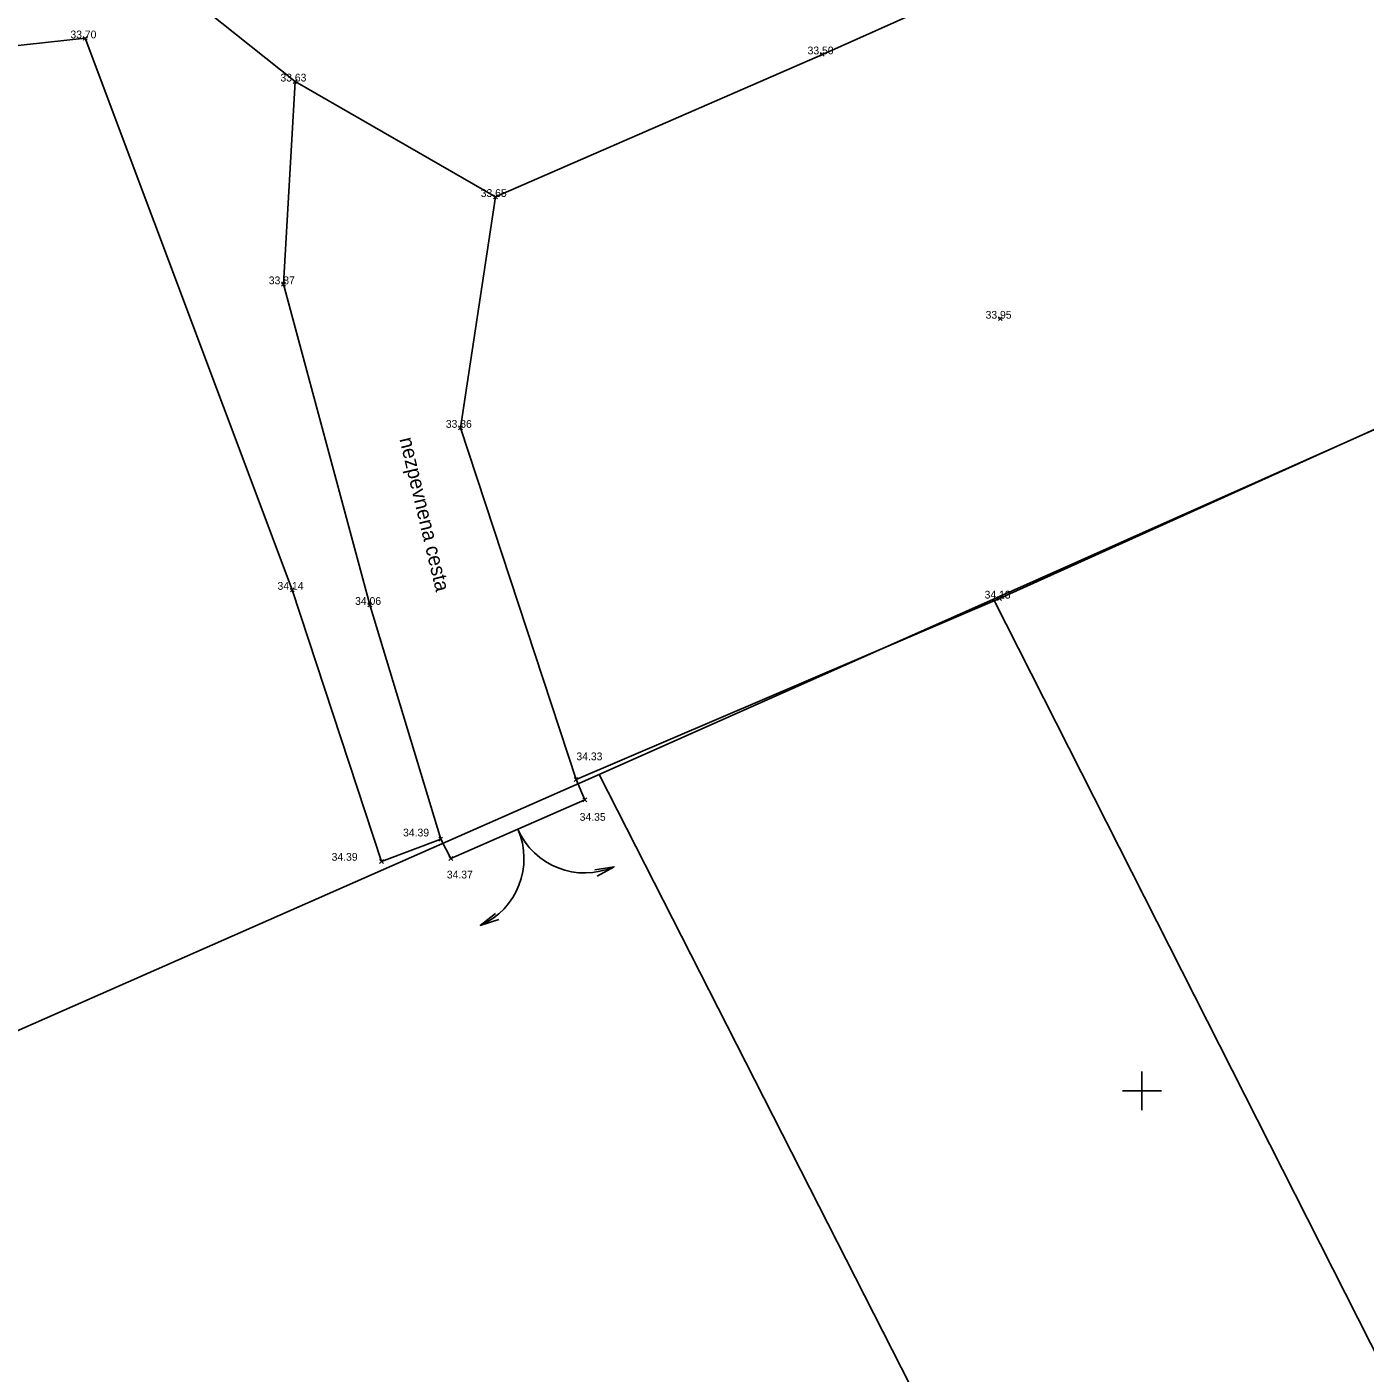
# Model space of a CAD drawing. Extents: x -772865 to -772533, y -1034366 to -1034132.
# Drawn here: x -772747.99 to -772720.4, y -1034305.82 to -1034278.06 of the extents above; entities that cross this region are included whole.
import ezdxf

# ---------------------------------------------------------------- set-up
doc = ezdxf.new("R2010")
doc.units = 0
for name, color, linetype in [('body', 7, 'Continuous'), ('KM_hranice', 7, 'Continuous'), ('mistni_popis', 7, 'Continuous'), ('oddeleni_ploch', 7, 'Continuous'), ('oploceni', 7, 'Continuous'), ('souradnicova_sit', 7, 'Continuous'), ('stromy_kere', 7, 'Continuous'), ('vyskove_koty', 7, 'Continuous')]:
    doc.layers.add(name, color=color, linetype=linetype)

msp = doc.modelspace()

# ---------------------------------------------------------------- linework, layer by layer
at = {"layer": 'body'}
for p, q in [((-772746.75, -1034278.34), (-772746.83, -1034278.26)), ((-772746.83, -1034278.34), (-772746.75, -1034278.26)), ((-772731.55, -1034278.67), (-772731.63, -1034278.59)), ((-772731.63, -1034278.67), (-772731.55, -1034278.59)), ((-772742.42, -1034279.23), (-772742.5, -1034279.15)), ((-772742.5, -1034279.23), (-772742.42, -1034279.15)), ((-772738.29, -1034281.61), (-772738.37, -1034281.53)), ((-772738.37, -1034281.61), (-772738.29, -1034281.53)), ((-772742.66, -1034283.41), (-772742.74, -1034283.33)), ((-772742.74, -1034283.41), (-772742.66, -1034283.33)), ((-772727.88, -1034284.12), (-772727.96, -1034284.04)), ((-772727.96, -1034284.12), (-772727.88, -1034284.04)), ((-772739.01, -1034286.37), (-772739.09, -1034286.29)), ((-772739.09, -1034286.37), (-772739.01, -1034286.29)), ((-772742.48, -1034289.71), (-772742.56, -1034289.63)), ((-772742.56, -1034289.71), (-772742.48, -1034289.63)), ((-772727.9, -1034289.89), (-772727.98, -1034289.81)), ((-772727.98, -1034289.89), (-772727.9, -1034289.81)), ((-772740.88, -1034290.02), (-772740.96, -1034289.94)), ((-772740.96, -1034290.02), (-772740.88, -1034289.94)), ((-772736.63, -1034293.62), (-772736.71, -1034293.54)), ((-772736.71, -1034293.62), (-772736.63, -1034293.54)), ((-772736.45, -1034294.04), (-772736.53, -1034293.96)), ((-772736.53, -1034294.04), (-772736.45, -1034293.96)), ((-772739.42, -1034294.85), (-772739.5, -1034294.77)), ((-772739.5, -1034294.85), (-772739.42, -1034294.77)), ((-772739.21, -1034295.25), (-772739.29, -1034295.17)), ((-772739.29, -1034295.25), (-772739.21, -1034295.17)), ((-772740.64, -1034295.31), (-772740.72, -1034295.23)), ((-772740.72, -1034295.31), (-772740.64, -1034295.23))]:
    msp.add_line(p, q, dxfattribs=at)
at = {"layer": 'KM_hranice'}
for p, q in [((-772728.06, -1034289.86), (-772677.97, -1034267.58)), ((-772728.06, -1034289.86), (-772736.19, -1034293.48)), ((-772709.03, -1034327.44), (-772728.06, -1034289.86)), ((-772736.19, -1034293.48), (-772790.73, -1034317.48)), ((-772720.86, -1034323.59), (-772736.19, -1034293.48))]:
    msp.add_line(p, q, dxfattribs=at)
at = {"layer": 'oddeleni_ploch'}
for p, q in [((-772738.33, -1034281.57), (-772739.05, -1034286.33)), ((-772739.05, -1034286.33), (-772736.67, -1034293.58)), ((-772736.67, -1034293.58), (-772736.67, -1034293.58))]:
    msp.add_line(p, q, dxfattribs=at)
for points in [[(-772689.63, -1034259.88), (-772704.53, -1034266.45), (-772719.18, -1034273.09), (-772731.59, -1034278.63), (-772738.33, -1034281.57), (-772742.46, -1034279.19), (-772747.03, -1034275.55), (-772755.44, -1034275.22), (-772763.58, -1034277.24), (-772782.03, -1034284.79), (-772793.82, -1034291.56), (-772799.88, -1034296.39), (-772802.42, -1034299.52), (-772804.8, -1034304.37)], [(-772742.46, -1034279.19), (-772742.7, -1034283.37), (-772740.92, -1034289.98), (-772739.46, -1034294.81)]]:
    msp.add_lwpolyline(points, dxfattribs=at)
at = {"layer": 'oploceni'}
msp.add_line((-772736.49, -1034294), (-772739.25, -1034295.21), dxfattribs=at)
for points in [[(-772580.41, -1034223.13), (-772594.37, -1034229.5), (-772606.44, -1034234.99), (-772615.35, -1034239.09), (-772626.89, -1034244.31), (-772647.29, -1034253.6), (-772657.19, -1034258.12), (-772675.87, -1034266.57), (-772700.9, -1034277.76), (-772711.36, -1034282.37), (-772727.94, -1034289.85)], [(-772736.49, -1034294), (-772736.67, -1034293.58), (-772727.94, -1034289.85)], [(-772740.68, -1034295.27), (-772739.46, -1034294.81), (-772739.25, -1034295.21)], [(-772736.235, -1034295.575), (-772735.886, -1034295.38), (-772736.281, -1034295.444)], [(-772738.329, -1034296.342), (-772738.644, -1034296.59), (-772738.264, -1034296.465)]]:
    msp.add_lwpolyline(points, dxfattribs=at)
for centre, start, end in [((-772739.25, -1034295.21), 293.7185, 23.6729), ((-772736.49, -1034294), 203.6729, 293.6273)]:
    msp.add_arc(centre, 1.507, start, end, dxfattribs=at)
at = {"layer": 'souradnicova_sit'}
for p, q in [((-772725, -1034299.6), (-772725, -1034300.4)), ((-772725.4, -1034300), (-772724.6, -1034300))]:
    msp.add_line(p, q, dxfattribs=at)
at = {"layer": 'stromy_kere'}
msp.add_lwpolyline([(-772740.68, -1034295.27), (-772742.52, -1034289.67), (-772746.79, -1034278.3), (-772762.65, -1034280.03), (-772770.31, -1034281.03), (-772770.41, -1034287.99)], dxfattribs=at)

# ---------------------------------------------------------------- texts
at = {"layer": 'mistni_popis'}
msp.add_text('nezpevnena cesta', height=0.3, rotation=283.4422, dxfattribs=at).set_placement((-772740.313, -1034286.561))
at = {"layer": 'vyskove_koty'}
for s, p in [('33.70', (-772747.095, -1034278.3)), ('33.50', (-772731.895, -1034278.63)), ('33.63', (-772742.765, -1034279.19)), ('33.65', (-772738.635, -1034281.57)), ('33.87', (-772743.005, -1034283.37)), ('33.95', (-772728.225, -1034284.08)), ('33.86', (-772739.355, -1034286.33)), ('34.14', (-772742.825, -1034289.67)), ('34.06', (-772741.225, -1034289.98)), ('34.13', (-772728.245, -1034289.85)), ('34.33', (-772736.662, -1034293.184)), ('34.35', (-772736.594, -1034294.432)), ('34.39', (-772740.236, -1034294.755)), ('34.39', (-772741.709, -1034295.256)), ('34.37', (-772739.334, -1034295.621))]:
    msp.add_text(s, height=0.16, dxfattribs=at).set_placement(p)

doc.saveas('drawing.dxf')
